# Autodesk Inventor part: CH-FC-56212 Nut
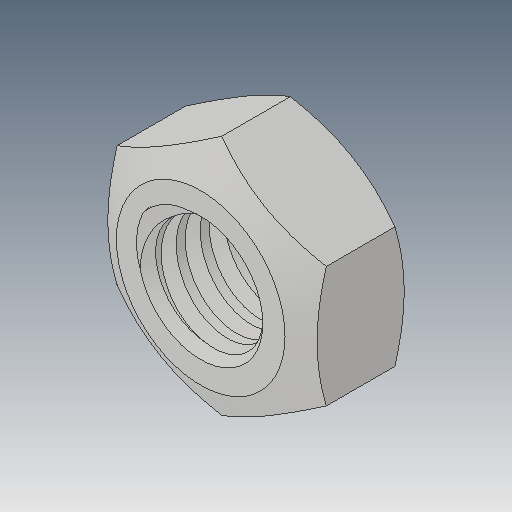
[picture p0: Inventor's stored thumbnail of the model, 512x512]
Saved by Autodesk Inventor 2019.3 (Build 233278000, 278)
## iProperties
Created: 2012-09
Part Number: CH-FC-56212 Nut
Material: Ogólny
Document SubType Name: Modeling
Designer: CADENGINEERING4
Density: 1 g/cm^3
Appearance: Domyślna
Author: CADENGINEERING4
Revision Number: ÈÎºÎ
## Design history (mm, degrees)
feature "¾µÏò1"
node "Bryła1"
